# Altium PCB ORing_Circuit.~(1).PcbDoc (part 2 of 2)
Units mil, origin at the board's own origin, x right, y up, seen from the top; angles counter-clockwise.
Board outline 1338.58 x 1378.07 mil, 8 copper layers (Top Layer, Layer 2, Layer 3, Layer 4, Layer 5, Layer 6, Layer 7, Bottom Layer), stack 50.047 mil thick; 34 components, 15 nets, 290 pads, 1023 vias.
Unrouted connection lines stored in the file: 1.
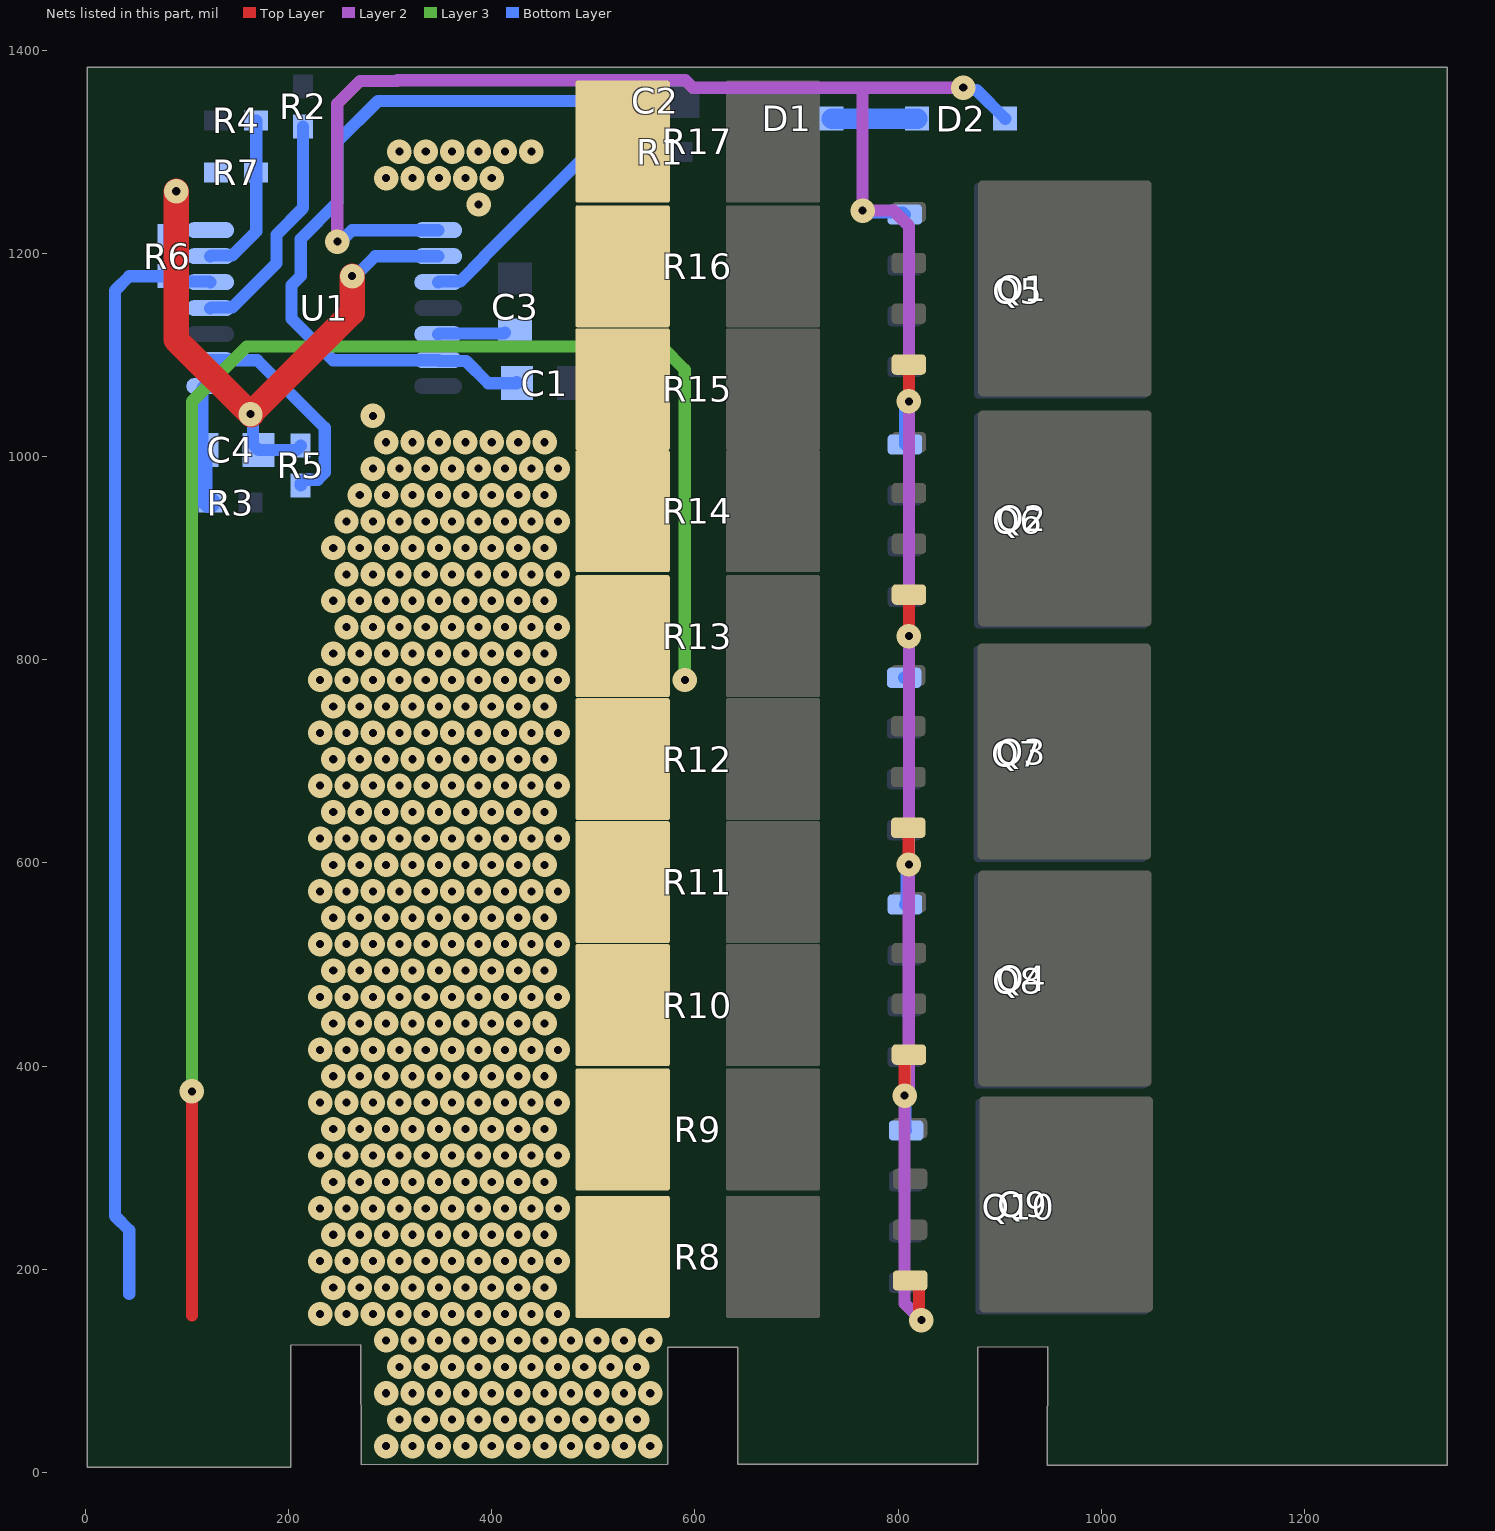
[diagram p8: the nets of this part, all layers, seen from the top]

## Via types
v1: diameter 24, hole 8, Top Layer to Bottom Layer, 1004 vias
v2: diameter 24, hole 8, Top Layer to Bottom Layer, tented both sides, 18 vias
v3: diameter 20, hole 10, Top Layer to Bottom Layer, 1 vias

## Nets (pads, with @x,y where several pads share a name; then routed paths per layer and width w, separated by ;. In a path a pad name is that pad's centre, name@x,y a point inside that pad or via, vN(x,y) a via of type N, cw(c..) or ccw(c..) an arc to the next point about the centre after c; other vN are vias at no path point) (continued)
Iout_SNS: R8.1 R9.1 R10.1 R11.1 R12.1 R13.1 R14.1 R15.1 R16.1 R17.1 | length 1721.9
  Top Layer w12: 104.89,154.61 v2(104.89,375.09)
  Layer 3 w12: v2(104.89,375.09) 104.89,1054.16 158.85,1108.13 567.3,1108.13 590,1085.43 v2(590,780)
  other v1: 296,26 322,26 348,26 374,26 400,26 426,26 452,26 478,26 504,26 530,26 556,26 309,52 335,52 361,52 387,52 413,52 439,52 465,52 491,52 517,52 543,52 296,78 322,78 348,78 374,78 400,78 426,78 452,78 478,78 504,78 530,78 556,78 309,104 335,104 361,104 387,104 413,104 439,104 465,104 491,104 517,104 543,104 296,130 322,130 348,130 374,130 400,130 426,130 452,130 478,130 504,130 530,130 556,130 231,156 257,156 283,156 309,156 335,156 361,156 387,156 413,156 439,156 465,156 244,182 270,182 296,182 322,182 348,182 374,182 400,182 426,182 452,182 231,208 257,208 283,208 309,208 335,208 361,208 387,208 413,208 439,208 465,208 244,234 270,234 296,234 322,234 348,234 374,234 400,234 426,234 452,234 231,260 257,260 283,260 309,260 335,260 361,260 387,260 413,260 439,260 465,260 244,286 270,286 296,286 322,286 348,286 374,286 400,286 426,286 452,286 231,312 257,312 283,312 309,312 335,312 361,312 387,312 413,312 439,312 465,312 244,338 270,338 296,338 322,338 348,338 374,338 400,338 426,338 452,338 231,364 257,364 283,364 309,364 335,364 361,364 387,364 413,364 439,364 465,364 244,390 270,390 296,390 322,390 348,390 374,390 400,390 426,390 452,390 231,416 257,416 283,416 309,416 335,416 361,416 387,416 413,416 439,416 465,416 244,442 270,442 296,442 322,442 348,442 374,442 400,442 426,442 452,442 231,468 257,468 283,468 309,468 335,468 361,468 387,468 413,468 439,468 465,468 244,494 270,494 296,494 322,494 348,494 374,494 400,494 426,494 452,494 231,520 257,520 283,520 309,520 335,520 361,520 387,520 413,520 439,520 465,520 244,546 270,546 296,546 322,546 348,546 374,546 400,546 426,546 452,546 231,572 257,572 283,572 309,572 335,572 361,572 387,572 413,572 439,572 465,572 244,598 270,598 296,598 322,598 348,598 374,598 400,598 426,598 452,598 231,624 257,624 283,624 309,624 335,624 361,624 387,624 413,624 439,624 465,624 244,650 270,650 296,650 322,650 348,650 374,650 400,650 426,650 452,650 231,676 257,676 283,676 309,676 335,676 361,676 387,676 413,676 439,676 465,676 244,702 270,702 296,702 322,702 348,702 374,702 400,702 426,702 452,702 231,728 257,728 283,728 309,728 335,728 361,728 387,728 413,728 439,728 465,728 244,754 270,754 296,754 322,754 348,754 374,754 400,754 426,754 452,754 231,780 257,780 283,780 309,780 335,780 361,780 387,780 413,780 439,780 465,780 244,806 270,806 296,806 322,806 348,806 374,806 400,806 426,806 452,806 257,832 283,832 309,832 335,832 361,832 387,832 413,832 439,832 465,832 244,858 270,858 296,858 322,858 348,858 374,858 400,858 426,858 452,858 257,884 283,884 309,884 335,884 361,884 387,884 413,884 439,884 465,884 244,910 270,910 296,910 322,910 348,910 374,910 400,910 426,910 452,910 257,936 283,936 309,936 335,936 361,936 387,936 413,936 439,936 465,936 270,962 296,962 322,962 348,962 374,962 400,962 426,962 452,962 283,988 309,988 335,988 361,988 387,988 413,988 439,988 465,988 296,1014 322,1014 348,1014 374,1014 400,1014 426,1014 452,1014 283,1040 387,1248 296,1274 322,1274 348,1274 374,1274 400,1274 309,1300 335,1300 361,1300 387,1300 413,1300 439,1300
NetC1_1: C1.1 C2.2 U1.13 | length 743.9
  Bottom Layer w12: C1.1@424.62,1073.08 C1.1@424.62,1072.09 396.58,1072.09 374.59,1094.09 347.97,1094.09 U1.13@347.25,1094.8 243.84,1094.8 203,1135.65 203,1168.55 211.97,1177.52 211.97,1214.19 248,1250.22 248,1310 287.99,1349.99 C2.2@533.44,1349.99
NetC3_2: C3.2 U1.12 | length 66.4
  Bottom Layer w12: U1.12@347.25,1120.4 347.97,1121.11 412.18,1121.11 C3.2@413,1121.93
NetC4_1: C4.1 R3.1 U1.1 | length 125.5
  Bottom Layer w12: C4.1@115.3,1006.49 115.3,1067.48 117.03,1069.21 U1.1@122.85,1069.21
  Bottom Layer w20: C4.1@115.3,1006.49 115.3,960.71 121.52,954.49 R3.1@123.17,954.49
NetD1_1: D1.1 D2.1 | length 84.4
  Bottom Layer w20: D1.1@734.31,1332.49 D2.1@818.69,1332.49
NetR1_1: R1.1 U1.10 | length 252.5
  Bottom Layer w12: U1.10@347.25,1171.58 347.97,1172.29 368.89,1172.29 392.39,1195.8 392.39,1196.54 495.34,1299.49 R1.1@546.32,1299.49
NetR2_1: R2.1 U1.4 | length 228.9
  Bottom Layer w12: U1.4@122.85,1145.99 123.56,1146.7 144.48,1146.7 188,1190.22 188,1218.32 214.28,1244.61 R2.1@214.28,1324.81
NetR4_1: R4.1 R7.2 U1.6 | length 164.4
  Bottom Layer w12: U1.6@122.85,1197.17 123.56,1197.88 144.48,1197.88 168.12,1221.53 R7.2@168.12,1279.33 R4.1@168.12,1330.51
NetR5_2: R5.2 U1.2 | length 214.7
  Bottom Layer w12: U1.2@122.85,1094.8 169.12,1094.8 235.68,1028.25 235.68,984.16 228.65,977.13 215.81,977.13 211.97,973.29 R5.2@211.97,971.32
ORing_CTRL: R6.2 U1.5 | length 1095.5
  Bottom Layer w12: 43.14,175.8 43.14,238.32 29.08,252.38 29.08,1163.42 43.14,1177.48 79.3,1177.48 84.49,1172.29 122.13,1172.29 U1.5@122.85,1171.58
ORing_Gate: D2.2 Q1.4 Q2.4 Q3.4 Q4.4 Q5.4 Q6.4 Q7.4 Q8.4 Q9.4 Q10.4 U1.8 | length 2588.9
  Top Layer w12: v2(806.37,370.88) 806.37,407.29 810.41,411.33 Q4.4@810.59,411.33 ; Q3.4@809.88,634.56 810.18,634.27 810.18,598.64 v2(810.47,598.35) ; Q1.4@810.47,1090.47 810.53,1090.41 810.53,1054.31 v2(810.59,1054.25) ; v2(810.59,823.17) Q2.4@810.59,864.09 ; Q9.4@811.75,188.95 816.49,188.95 820.53,184.91 820.53,152.3 v2(822.82,150)
  Layer 2 w12: v2(248,1211.49) 248,1347.08 270.62,1369.7 306.62,1369.7 307.28,1370.36 590.64,1370.36 598.01,1362.99 765,1362.99 ; v2(822.82,150) 806.37,166.45 v2(806.37,370.88) 806.37,374.12 810.47,378.22 v2(810.47,598.35) 810.53,598.41 810.53,823.11 v2(810.59,823.17) v2(810.59,1054.25) 810.59,1226.83 795.42,1242 v2(765,1242) 765,1362.99 ; v2(864,1362.99) 765,1362.99
  Bottom Layer w12: v2(248,1211.49) 251.25,1211.49 262.51,1222.76 U1.8@347.25,1222.76 ; v2(765,1242) 766.92,1240.08 804.55,1240.08 Q5.4@806.47,1238.15 ; Q7.4@805.88,782.25 806.55,782.25 810.59,786.29 v2(810.59,823.17) ; v2(806.37,370.88) 807.06,370.19 807.06,337.33 Q10.4@807.75,336.64 ; Q8.4@806.59,559.02 808.53,560.96 808.53,596.41 v2(810.47,598.35) ; Q6.4@806.59,1011.77 806.59,1047.01 810.59,1051.01 v2(810.59,1054.25) ; v2(864,1362.99) 866.3,1360.69 877.1,1360.69 D2.2@905.31,1332.49
SGND: C4.2 R5.1 R6.1 R7.1 U1.7 U1.9 | length 606.1
  Top Layer w12: v2@260.22,1179.78 v2(262.51,1177.48)
  Top Layer w25: v2(89.49,1261.06) 89.49,1114.7 v2(162.54,1041.66) ; v2@163.33,1040.86 v2(162.54,1041.66) ; v2(262.51,1177.48) 262.51,1141.63 v2(162.54,1041.66)
  Bottom Layer w12: v2(162.54,1041.66) 164.84,1039.36 164.84,1012.07 C4.2@170.41,1006.49 208.12,1006.49 211.97,1010.33 R5.1@211.97,1010.69 ; v2(262.51,1177.48) 265.57,1177.48 285.26,1197.17 U1.9@347.25,1197.17
pads on no net: Q1.9@888.82,1072.06 Q1.9@888.82,1258.87 Q1.9@900.43,1113.11 Q1.9@900.43,1165.47 Q1.9@900.43,1217.83 Q1.9@945.71,1113.11 Q1.9@945.71,1165.47 Q1.9@945.71,1217.83 Q1.9@951.02,1165.47 Q1.9@990.99,1113.11 Q1.9@990.99,1165.47 Q1.9@990.99,1217.83 Q2.9@888.93,845.68 Q2.9@888.93,1032.49 Q2.9@900.55,886.73 Q2.9@900.55,939.09 Q2.9@900.55,991.45 Q2.9@945.82,886.73 Q2.9@945.82,939.09 Q2.9@945.82,991.45 Q2.9@951.14,939.09 Q2.9@991.1,886.73 Q2.9@991.1,939.09 Q2.9@991.1,991.45 Q3.9@888.23,616.16 Q3.9@888.23,802.97 Q3.9@899.84,657.2 Q3.9@899.84,709.56 Q3.9@899.84,761.92 Q3.9@945.12,657.2 Q3.9@945.12,709.56 Q3.9@945.12,761.92 Q3.9@950.43,709.56 Q3.9@990.39,657.2 Q3.9@990.39,709.56 Q3.9@990.39,761.92 Q4.9@888.93,392.93 Q4.9@888.93,579.74 Q4.9@900.55,433.97 Q4.9@900.55,486.33 Q4.9@900.55,538.7 Q4.9@945.82,433.97 Q4.9@945.82,486.33 Q4.9@945.82,538.7 Q4.9@951.14,486.33 Q4.9@991.1,433.97 Q4.9@991.1,486.33 Q4.9@991.1,538.7 Q5.9@884.82,1069.75 Q5.9@884.82,1256.56 Q5.9@896.43,1110.79 Q5.9@896.43,1163.15 Q5.9@896.43,1215.52 Q5.9@941.71,1110.79 Q5.9@941.71,1163.15 Q5.9@941.71,1215.52 Q5.9@947.02,1163.15 Q5.9@986.99,1110.79 Q5.9@986.99,1163.15 Q5.9@986.99,1215.52 Q6.9@884.93,843.37 Q6.9@884.93,1030.18 Q6.9@896.55,884.41 Q6.9@896.55,936.77 Q6.9@896.55,989.14 Q6.9@941.82,884.41 Q6.9@941.82,936.77 Q6.9@941.82,989.14 Q6.9@947.14,936.77 Q6.9@987.1,884.41 Q6.9@987.1,936.77 Q6.9@987.1,989.14 Q7.9@884.23,613.84 Q7.9@884.23,800.65 Q7.9@895.84,654.89 Q7.9@895.84,707.25 Q7.9@895.84,759.61 Q7.9@941.12,654.89 Q7.9@941.12,707.25 Q7.9@941.12,759.61 Q7.9@946.43,707.25 Q7.9@986.39,654.89 Q7.9@986.39,707.25 Q7.9@986.39,759.61 Q8.9@884.93,390.61 Q8.9@884.93,577.42 Q8.9@896.55,431.66 Q8.9@896.55,484.02 Q8.9@896.55,536.38 Q8.9@941.82,431.66 Q8.9@941.82,484.02 Q8.9@941.82,536.38 Q8.9@947.14,484.02 Q8.9@987.1,431.66 Q8.9@987.1,484.02 Q8.9@987.1,536.38 Q9.9@890.1,170.55 Q9.9@890.1,357.36 Q9.9@901.71,211.59 Q9.9@901.71,263.95 Q9.9@901.71,316.31 Q9.9@946.99,211.59 Q9.9@946.99,263.95 Q9.9@946.99,316.31 Q9.9@952.3,263.95 Q9.9@992.27,211.59 Q9.9@992.27,263.95 Q9.9@992.27,316.31 Q10.9@886.1,168.23 Q10.9@886.1,355.04 Q10.9@897.71,209.28 Q10.9@897.71,261.64 Q10.9@897.71,314 Q10.9@942.99,209.28 Q10.9@942.99,261.64 Q10.9@942.99,314 Q10.9@948.3,261.64 Q10.9@988.27,209.28 Q10.9@988.27,261.64 Q10.9@988.27,314 U1.3 U1.14

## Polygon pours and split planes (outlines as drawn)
SGND on Layer 5 "SGND" (solid, remove dead copper, pour order 85): 50,1280 10,1240 10,516.23 143.65,382.58 143.65,199.68 163.33,180 173.02,180 183.02,190 183.02,1038.88 279.18,1135.04 279.18,1179.78 275.22,1179.78 175,1280
Iout_SNS on Layer 5 "LAYER_5_IOUT_SNS_P055" (solid, remove dead copper, pour order 55): 586.77,810 569.71,792.95 569.71,767.05 586.77,750 586.77,128.23 589.49,125.51 573.26,125.51 573.26,5.91 271.31,7.89 271.31,125.49 202,125.49 202,1367.64 217.43,1383.07 586.77,1383.07
12VB on Layer 5 "LAYER_5_12VB_P069" (solid, remove dead copper, pour order 69): 864,1383.07 864,172.44 912.83,123.61 946.83,123.74 946.83,7.3 1340.53,7.3 1340.53,1302.71 1261.79,1381.45
12VA on Layer 5 "LAYER_5_12VA_P074" (solid, remove dead copper, pour order 74): 613,780 635.96,757.04 635.96,732.96 613,710 613,128.87 608.22,124.09 642.28,124.09 642.28,7.02 878.86,6.85 878.86,123.48 879,145 837,145 835,147 838,150 838,1382.93 613,1385
no net on Top Solder "NONET_L-01_P-001" (solid): 271.31,126.41 271.31,7.89 573.26,5.91 573.26,125.51
no net on Top Solder "NONET_L-01_P-001" (solid): 642.11,129.15 642.11,6.85 878.86,6.85 877.42,129.15
no net on Top Solder "NONET_L-01_P-001" (solid): 946.83,130.88 946.83,7.3 1262.4,7.3 1261.17,130.88
no net on Top Solder "NONET_L-01_P-001" (solid): 1.94,125.49 201,125.49 201,7.74 202,6.74 1.94,6.74
no net on Top Solder "NONET_L-01_P-001" (solid): 4,222 189,222 189,105.07 190.07,104 174.73,88.66 1.94,88.66
no net on Top Solder "NONET_L-01_P-001" (solid): 296,1383.07 296,970.29 202,876.29 202,159.86 238.99,122.87 271.31,122.87 271.31,7.74 273.28,5.77 573.26,5.77 573.26,146 479,146 478,145 477,146 477,1385
no net on Top Solder "NONET_L-01_P-001" (solid): 907,1282 915,1274 1063,1274 1063,130.88 1055.56,123.44 945.6,123.44 945.6,7 1340.53,7.37 1340.53,1302.71 1260.16,1383.07 907,1383.07
SGND on Bottom Layer "BOTTOM_LAYER_SGND_P041" (solid, remove dead copper, pour order 41): 54.78,1202.33 55.13,1201.98 148.57,1201.98 148.57,1301.31 147.65,1302.23 75.01,1302.23 54.78,1282
Iout_SNS on Bottom Layer "BOTTOM_LAYER_IOUT_SNS_P058" (solid, remove dead copper, pour order 58): 586.77,810 563.3,786.53 563.3,752.82 586.77,729.35 586.77,128.09 589.49,125.36 573.26,125.36 573.26,5.77 271.31,7.74 271.31,125.34 202,125.34 202,1027.23 586.77,1027.23
12VA on Bottom Layer "BOTTOM_LAYER_12VA_P077" (solid, remove dead copper, pour order 77): 613,780 634.73,758.27 634.73,740.09 613,718.35 613,128.87 608.22,124.09 642.28,124.09 642.28,7.02 642.11,6.85 878.86,6.85 878.86,123.48 879,123.62 879,145 837,145 835,147 838,150 838,1382.93 613,1385
12VB on Bottom Layer "BOTTOM_LAYER_12VB_P072" (solid, remove dead copper, pour order 72): 864,1383.07 864,172.44 912.83,123.61 946.83,123.74 946.83,7.3 1340.53,7.3 1340.53,1302.71 1261.79,1381.45
SGND on Layer 6 "SGND" (solid, remove dead copper, pour order 83): 50,1280 10,1240 10,516.23 143.65,382.58 143.65,199.68 163.33,180 173.02,180 183.02,190 183.02,1038.88 279.18,1135.04 279.18,1179.78 275.22,1179.78 175,1280
Iout_SNS on Layer 6 "LAYER_6_IOUT_SNS_P056" (solid, remove dead copper, pour order 56): 586.77,810 571.68,794.91 571.68,765.09 586.77,750 586.77,128.23 589.49,125.51 573.26,125.51 573.26,5.91 271.31,7.89 271.31,125.49 202,125.49 202,1367.64 217.43,1383.07 586.77,1383.07
12VB on Layer 6 "LAYER_6_12VB_P070" (solid, remove dead copper, pour order 70): 864,1383.07 864,172.44 912.83,123.61 946.83,123.74 946.83,7.3 1340.53,7.3 1340.53,1302.71 1261.79,1381.45
12VA on Layer 6 "LAYER_6_12VA_P075" (solid, remove dead copper, pour order 75): 613,784.04 640,757.04 640,737 613,710 613,128.87 608.22,124.09 642.28,124.09 642.28,7.02 642.11,6.85 878.86,6.85 878.86,123.48 879,123.62 879,145 837,145 835,147 838,150 838,1382.93 613,1385
no net on Bottom Solder "NONET_L-01_P-001" (solid): 1.94,125.49 202,125.49 202,6.74 1.94,6.74
no net on Bottom Solder "NONET_L-01_P-001" (solid): 4,222 189,222 189,105.07 190.07,104 174.73,88.66 1.94,88.66
no net on Bottom Solder "NONET_L-01_P-001" (solid): 271.31,126.41 271.31,7.89 573.26,5.91 573.26,125.51
no net on Bottom Solder "NONET_L-01_P-001" (solid): 642.11,129.15 642.11,6.85 878.86,6.85 877.42,129.15
no net on Bottom Solder "NONET_L-01_P-001" (solid): 946.83,130.88 946.83,7.3 1262.4,7.3 1261.17,130.88
no net on Bottom Solder "NONET_L-01_P-001" (solid): 296,1029.49 296,973.98 202,879.98 202,163.55 238.99,126.56 271.31,126.56 271.31,11.43 273.28,9.46 573.26,9.46 573.26,149.69 573.26,1032.44
no net on Bottom Solder "NONET_L-01_P-001" (solid): 946.79,1277.85 1064.19,1277.85 1064.19,134.73 1056.75,127.29 946.79,127.29 946.79,10.85 1340.53,11.21 1340.53,1307.75 1261.35,1386.92 946.79,1386.92
no net on Bottom Solder "NONET_L-01_P-001" (solid): 613,1211.49 613,123.48 613.61,122.87 777,122.87 777,1211.49
SGND on Top Layer "SGND" (solid, remove dead copper, pour order 79): 50,1280 10,1240 10,516.23 143.65,382.58 143.65,90 183.02,90 183.02,1038.88 279.18,1135.04 279.18,1179.78 275.22,1179.78 175,1280
Iout_SNS on Top Layer "TOP_LAYER_IOUT_SNS_P051" (solid, remove dead copper, pour order 51): 573.26,5.91 573.26,125.51 589.49,125.51 586.77,128.23 586.77,1383.07 217.43,1383.07 202,1367.64 202,125.49 271.31,125.49 271.31,7.89
12VA on Top Layer "TOP_LAYER_12VA_P059" (solid, remove dead copper, pour order 59): 613,1385 613,128.87 608.22,124.09 642.28,124.09 642.28,7.02 642.11,6.85 878.86,6.85 878.86,123.48 879,123.62 879,145 837,145 835,147 838,150 838,1382.93
12VB on Top Layer "TOP_LAYER_12VB_P063" (solid, remove dead copper, pour order 63): 864,1383.07 864,172.44 912.83,123.61 946.83,123.74 946.83,7.3 1340.53,7.3 1340.53,1302.71 1261.79,1381.45
Iout_SNS on Layer 2 "LAYER_2_IOUT_SNS_P052" (solid, remove dead copper, pour order 52): 586.77,810 569.71,792.95 569.71,765.95 586.77,748.9 586.77,741.65 586.77,128.23 589.49,125.51 573.26,125.51 573.26,5.91 271.31,7.89 271.31,125.49 202,125.49 177.51,150 20,150 10,160 10,1110.92 39.09,1140.01 202,1139.91 202,1367.64 217.43,1383.07 586.77,1383.07
12VA on Layer 2 "LAYER_2_12VA_P062" (solid, remove dead copper, pour order 62): 613,780 640,753 640,740 613.47,713.47 613,710 613,128.87 608.22,124.09 642.28,124.09 642.28,7.02 642.11,6.85 878.86,6.85 878.86,123.48 879,123.62 879,145 837,145 835,147 838,150 838,1382.93 613,1385
12VB on Layer 2 "LAYER_2_12VB_P066" (solid, remove dead copper, pour order 66): 864,1383.07 864,172.44 912.83,123.61 946.83,123.74 946.83,7.3 1340.53,7.3 1340.53,1302.71 1261.79,1381.45
Iout_SNS on Layer 3 "LAYER_3_IOUT_SNS_P053" (solid, remove dead copper, pour order 53): 573.26,5.91 573.26,125.51 573.26,1087 202,1087 202,125.49 271.31,125.49 271.31,7.89
12VA on Layer 3 "LAYER_3_12VA_P064" (solid, remove dead copper, pour order 64): 640,757.04 640,728.65 613,701.65 613,128.87 608.22,124.09 642.28,124.09 642.28,7.02 878.86,6.85 878.86,123.48 879,145 837,145 835,147 838,150 838,1382.93 640,1384.75
12VB on Layer 3 "LAYER_3_12VB_P067" (solid, remove dead copper, pour order 67): 864,1383.07 864,172.44 912.83,123.61 946.83,123.74 946.83,7.3 1340.53,7.3 1340.53,1302.71 1261.79,1381.45
Iout_SNS on Layer 4 "LAYER_4_IOUT_SNS_P054" (solid, remove dead copper, pour order 54): 586.77,807.05 569.71,790 570,789.71 570,758.41 586.77,741.65 586.77,128.23 589.49,125.51 573.26,125.51 573.26,5.91 271.31,7.89 271.31,125.49 202,125.49 202,128 180,150 20,150 10,160 10,1110 40,1140 202,1140 202,1367.64 217.43,1383.07 586.77,1383.07
12VB on Layer 4 "LAYER_4_12VB_P068" (solid, remove dead copper, pour order 68): 864,1383.07 864,172.44 912.83,123.61 946.83,123.74 946.83,7.3 1340.53,7.3 1340.53,1302.71 1261.79,1381.45
12VA on Layer 4 "LAYER_4_12VA_P073" (solid, remove dead copper, pour order 73): 613,780 640,753 640,737 613,710 613,128.87 608.22,124.09 642.28,124.09 642.28,7.02 642.11,6.85 878.86,6.85 878.86,123.48 879,123.62 879,145 837,145 835,147 838,150 838,1382.93 613,1385
SGND on Layer 7 "SGND" (solid, remove dead copper, pour order 81): 50,1280 10,1240 10,516.23 143.65,382.58 143.65,199.68 163.33,180 173.02,180 183.02,190 183.02,1038.88 279.18,1135.04 279.18,1179.78 275.22,1179.78 175,1280
Iout_SNS on Layer 7 "LAYER_7_IOUT_SNS_P057" (solid, remove dead copper, pour order 57): 586.77,810 569.71,792.95 569.71,765.92 586.77,750 586.77,128.23 589.49,125.51 573.26,125.51 573.26,5.91 271.31,7.89 271.31,125.49 202,125.49 202,1367.64 217.43,1383.07 586.77,1383.07
12VB on Layer 7 "LAYER_7_12VB_P071" (solid, remove dead copper, pour order 71): 862.77,1382.78 862.77,172.14 911.6,123.31 945.6,123.44 945.6,7 1340.53,7 1340.53,1301.19 1260.56,1381.15
12VA on Layer 7 "LAYER_7_12VA_P076" (solid, remove dead copper, pour order 76): 613,780 635.96,757.04 635.96,732.96 613,710 613,128.87 608.22,124.09 642.28,124.09 642.28,7.02 878.86,6.85 878.86,123.48 879,145 837,145 835,147 838,150 838,1382.93 613,1385

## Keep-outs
Keep-Out Layer:
  text ".Layer_Name" at 577,-858.49 h60

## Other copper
Top Layer:
  region net Iout_SNS: 121.02,202.68 109.21,214.49 93.46,214.49 81.65,202.68 81.65,5.83 121.02,5.83
  region net SGND: 183.02,201.68 171.21,213.49 155.46,213.49 143.65,201.68 143.65,4.83 183.02,4.83
  region net 12VA: 60.68,202.19 48.87,214 33.13,214 21.32,202.19 21.32,5.34 60.68,5.34
  text ".Layer_Name" at 577,-858.49 h60
Bottom Layer:
  region net 12VS: 81.06,202.67 92.87,214.48 108.62,214.48 120.43,202.67 120.43,5.82 81.06,5.82
  region net SGND: 143.23,202.61 155.04,214.42 170.79,214.42 182.6,202.61 182.6,5.76 143.23,5.76
  region net ORing_CTRL: 21.32,202.67 33.13,214.48 48.87,214.48 60.68,202.67 60.68,5.82 21.32,5.82
  text ".Layer_Name" at 577,-858.49 h60

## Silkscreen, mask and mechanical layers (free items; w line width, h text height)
Top Overlay:
  text ".Layer_Name" at 577,-858.49 h60
Bottom Overlay:
  text "ORING DC" at 23.46,248 h80 r270
  text "PMP23126 RevA" at 93.46,248 h80 r270
  text ".Layer_Name" at 577,-858.49 h60
Top Paste:
  text ".Layer_Name" at 577,-858.49 h60
Bottom Paste:
  text ".Layer_Name" at 577,-858.49 h60
Top Solder:
  text ".Layer_Name" at 577,-858.49 h60
  text ".Layer_Name" at 577,-858.49 h60
Bottom Solder:
  text ".Layer_Name" at 577,-858.49 h60
Drill Guide:
  text ".Layer_Name" at 577,-858.49 h60
M1 Board Outline:
  lines w10: 202,5 1.94,5 1.94,1383.07 1340.53,1383.07 1340.53,7 946.83,7.25 947.33,123.74 878.33,123.48 878.33,7.94 642.11,7.94 642.11,123.48 573.11,123.48 573.42,7.94 271.31,7.69 271.31,125.8 ; 202,7 202,125.11 ; 202,125.23 271,125.49
  text ".Layer_Name" at 577,-858.49 h60
M2 Board Dimensions:
  rectangle: 125,-400 500,-275
  rectangle: 0,-275 125,-150
  lines w7: 0,-275 1000,-275 ; 125,-400 125,-150 ; 250,-400 250,-150 ; 500,-400 500,-150 ; 750,-400 750,-150 ; 0,-400 0,-150 1000,-150 1000,-400 0,-400
  text ".Layer_Name" at 577,-858.49 h60
M3 3D STEP Top:
  text ".Layer_Name" at 577,-858.49 h60
M4 3D STEP Bottom:
  text ".Layer_Name" at 577,-858.49 h60
M5 Assembly Top:
  lines w10: -292,-930.17 6308,-930.17 ; -292,-726.83 6310,-726.83 ; -292,-523.5 -292,-1133.5 3713,-1133.5 6310,-1133.5 6310,-523.5 -291.5,-523.5 -291.5,-1133.5 1284,-1133.5 ; 2173,-1133.5 2173,-523.5 ; 3440,-726.83 3440,-523.5 ; 4280,-726.83 4280,-523.5 ; 4902,-1140 4902,-937.17
  text "COMPONENTS MARKED 'DNP' SHOULD NOT BE POPULATED." at 1153.5,-318.5 h60
  text "ASSEMBLY VARIANT:" at 1153,-434 h60
  text ".VariantName" at 2189,-434 h60
  text "PCB VIEWED FROM TOP SIDE" at -228.5,-655.67 h60
  text "BOARD #:" at 2248,-655.67 h60
  text ".PRJ_Number" at 2793.5,-655.67 h60
  text "REV:" at 3638,-655.67 h60
  text ".PCB_Rev" at 3929.5,-655.67 h60
  text "SVN REV:" at 4476,-655.67 h60
  text ".VersionControl_RevNumber" at 4982,-655.67 h60
  text "TID #:" at 2248,-859 h60
  text ".TID" at 2793.5,-859 h60
  text "PLOT NAME =" at -228.5,-1064.34 h60
  text ".plot_File_Name" at 577,-1064.34 h60
  text "GENERATED    :" at 2250,-1064.34 h60
  text ".Print_Date" at 3119.5,-1064.34 h60
  text ".Print_Time" at 3848.5,-1064.34 h60
  text "TEXAS INSTRUMENTS" at 5113,-1064.34 h60
M6 Assembly Bottom:
  lines w10: -292.5,-727.33 6309.5,-727.33 ; -290.5,-930.67 6309.5,-930.67 ; 1115.5,-1140.5 1115.5,-937.67 ; 1737.5,-727.33 1737.5,-524 ; 2577.5,-727.33 2577.5,-524 ; 3844.5,-1134 3844.5,-524 ; 4733.5,-1134 6309,-1134 6309,-524 -292.5,-524 -292.5,-1134 2304.5,-1134 6309.5,-1134 6309.5,-524
  text "COMPONENTS MARKED 'DNP' SHOULD NOT BE POPULATED." at 6102,-318 h60
  text ".VariantName" at 5058,-434 h60
  text "ASSEMBLY VARIANT:" at 6097,-434 h60
  text ".VersionControl_RevNumber" at 1035.5,-656.17 h60
  text "SVN REV:" at 1541.5,-656.17 h60
  text ".PCB_Rev" at 2088,-656.17 h60
  text "REV:" at 2379.5,-656.17 h60
  text ".PRJ_Number" at 3224,-656.17 h60
  text "BOARD #:" at 3769.5,-656.17 h60
  text "PCB VIEWED FROM BOTTOM SIDE" at 6246,-656.17 h60
  text ".TID" at 3224,-859.5 h60
  text "TID #:" at 3769.5,-859.5 h60
  text "TEXAS INSTRUMENTS" at 904.5,-1064.84 h60
  text ".Print_Time" at 2169,-1064.84 h60
  text ".Print_Date" at 2898,-1064.84 h60
  text "GENERATED    :" at 3767.5,-1064.84 h60
  text ".plot_File_Name" at 5440.5,-1064.84 h60
  text "PLOT NAME =" at 6246,-1064.84 h60
M9 Title Sheet:
  drawing of 57 lines, arcs and shapes, not listed
  text "1" at 739.84,8036.5 h70
  text "2" at 3235.5,8036.5 h70
  text "3" at 5724.84,8036.5 h70
  text "4" at 8231.51,8036.5 h70
  text "5" at 10730.5,8036.5 h70
  text "6" at 13235.5,8036.5 h70
  text "A" at -416.5,6893.5 h70
  text "A" at 14383.5,6893.5 h70
  text "B" at -416.5,4513.5 h70
  text "B" at 14383.5,4513.5 h70
  text "C" at -416.5,2138.5 h70
  text "C" at 14383.5,2138.5 h70
  text "PROJECT TITLE:" at 11343.5,277.5 h45
  text ".PRJ_Title" at 11393.5,144.17 h70
  text "DESIGNED FOR:" at 11343.5,-23.5 h45
  text ".PRJ_Customer" at 11393.5,-163.5 h70
  text "D" at -416.5,-231.5 h70
  text "D" at 14383.5,-231.5 h70
  text "FILE NAME:" at 11343.5,-323.5 h45
  text ".PCB_File_Name_No_Path" at 11393.5,-443.5 h70
  text "Texas Instruments (TI) and/or its licensors do not warrant the accuracy or completeness of this specification" at 6374,-605.34 h45
  text "ENGINEER:" at 11343.5,-613.5 h45
  text "LAYOUT BY:" at 12848.5,-613.5 h45
  text "or any information contained therein. TI and/or its licensors do not warrant that this design will meet" at 6329.01,-718 h45
  text ".PRJ_Engineer" at 11393.5,-768.49 h70
  text ".PCB_Layout" at 12899,-768.49 h70
  text "the specifications, will be suitable for your application or fit for any particular purpose, or will operate in" at 6329.01,-830.67 h45
  text ".Layer_Name" at 577,-858.49 h60
  text "ALTIUM DESIGNER VERSION:" at 12848.5,-923.5 h45
  text "an implementation. TI and/or its licensors do not warrant that the design is production worthy. You should" at 6329.01,-943.33 h45
  text "completely validate and test your design implementation to confirm the system functionality for your application." at 6374,-1056 h45
  text ".print_Scale" at 11393.5,-1056.83 h70
  text ".Application_BuildNumber" at 12899,-1056.83 h70
  text "1" at 739.84,-1263.5 h70
  text "2" at 3235.5,-1263.5 h70
  text "3" at 5724.84,-1263.5 h70
  text "4" at 8231.51,-1263.5 h70
  text "5" at 10730.5,-1263.5 h70
  text "6" at 13235.5,-1263.5 h70
M10 Fab Notes:
  drawing of 189 lines, arcs and shapes, not listed
  text "DESIGN INFORMATION" at 12382.02,6356.17 h60
  text "MIN. TRACK WIDTH:" at 11737.46,6224.05 h60
  text "8" at 12833.7,6224.05 h60
  text "MIL" at 12988.46,6224.05 h60
  text "7.874" at 12667.32,6102.36 h60
  text "MIN. CLEARANCE:" at 11737.46,6099.92 h60
  text "MIL" at 12988.46,6099.92 h60
  text "MIN. VIA PAD SIZE:" at 11737.46,5975.8 h60
  text "24" at 12803.71,5975.8 h60
  text "MIL" at 12988.46,5975.8 h60
  text "0.05mm (2MIL)" at 12432.46,5845.9 h60
  text "MINIMUM ANNULAR RING" at 11408.23,5837.67 h60
  text "EXTERNAL" at 13140.46,5837.67 h60
  text "PER" at 11608.23,5727.55 h60
  text "IPC-D-275 CLASS 2 LEVEL C" at 11828.23,5727.54 h60
  text "MIL, HOLES" at 13316.46,5627.07 h60
  text "+/-" at 12924,5618.48 h60
  text "+/-" at 13778,5618.48 h60
  text "REGISTRATION TOLERANCES:" at 11408.23,5617.42 h60
  text "METAL" at 12608,5617.42 h60
  text "5" at 13184.2,5617.42 h60
  text "3" at 14017.2,5617.42 h60
  text "MIL" at 14133.46,5617.42 h60
  text "HOLE SIZE TOLERANCE (UNLESS OTHERWISE SPECIFIED):" at 11408.23,5519.1 h60
  text "+/-" at 13778,5516.23 h60
  text "3" at 14017.2,5515.17 h60
  text "MIL" at 14133.46,5515.17 h60
  text "MATERIAL:" at 11333.46,5377.52 h60
  text "FR-4 High Tg" at 12319.9,5249 h60
  text "X" at 12175.46,5241.01 h60
  text "FR-408" at 11754.46,5236.49 h60
  text "OTHER" at 13242.46,5236.49 h60
  text "62 MIL (1.6mm) +/-10%" at 12074.56,5093.46 h60
  text "X" at 11954.46,5091.01 h60
  text "THICKNESS:" at 11408.23,5085.24 h60
  text "OTHER" at 13359.46,5085.24 h60
  text "TOLERANCE:" at 11408.23,4946.92 h60
  text "X" at 12256.46,4946.92 h60
  text "ANSI IPC-6012 TYPE 3 CLASS 2" at 12434.48,4946.92 h60
  text "OTHER +/-" at 12434.46,4802.73 h60
  text "BOW & TWIST:" at 11408.23,4657.54 h60
  text "X" at 12256.46,4657.54 h60
  text "ANSI IPC-6012 TYPE 3 CLASS 2" at 12434.48,4657.54 h60
  text "OTHER +/-" at 12434.46,4510.85 h60
  text "DRILLING:" at 11333.46,4380.23 h60
  text "NC_DRILL FILES" at 13094.46,4275.04 h60
  text "REFERENCE:" at 11408.23,4271.1 h60
  text "X" at 12065.46,4271.01 h60
  text "AS SHOWN" at 12243.46,4271.1 h60
  text "X" at 12966.46,4271.1 h60
  text "OTHER" at 13392.46,4128.85 h60
  text "PTH COPPER THICKNESS:" at 11407.91,4125.32 h60
  text "X" at 12547.14,4125.32 h60
  text "20-30 um" at 12675.14,4125.32 h60
  text "BOARD FINISH:" at 11333.46,3977.73 h60
  text "SILKSCREEN:" at 11488.68,3867.6 h60
  text "X" at 12446.46,3867.6 h60
  text "TOP" at 12563.46,3867.6 h60
  text "X" at 12956.46,3867.6 h60
  text "BOTTOM" at 13074.46,3867.6 h60
  text "SILKSCREEN COLOR:" at 11488.68,3712.41 h60
  text "X" at 12445.46,3712.41 h60
  text "WHITE" at 12563.46,3712.41 h60
  text "OTHER" at 13074.46,3712.41 h60
  text "X" at 12576.46,3568.96 h60
  text "GREEN" at 12694.46,3568.96 h60
  text "OTHER" at 13312.46,3568.96 h60
  text "SOLDER RESIST COLOR:" at 11488.68,3562.1 h60
  text "X" at 12576.46,3414.71 h60
  text "MATTE" at 12694.46,3414.71 h60
  text "SEMI-GLOSS" at 13312,3414.07 h60
  text "IMMERSION GOLD (ENIG)" at 12394.46,3241.94 h60
  text "ENEPIG" at 13732,3234.72 h60
  text "SURFACE FINISH:" at 11333.46,3233.72 h60
  text "X" at 12216.46,3233.72 h60
  text "IMM. TIN/SILVER OR EQUIV" at 11663,3096.4 h60
  text "OTHER" at 13094.46,3092.47 h60
  text "ARRAY/PANEL:" at 11333.46,2937.09 h60
  text "CUT AND TRIM PER M1 BOARD OUTLINE" at 12394.46,2928.87 h60
  text "N.C. ROUTE" at 12394.46,2792.9 h60
  text "X" at 13082.46,2792.9 h60
  text "V. SCORE" at 13260.46,2792.9 h60
  text "CERTIFICATION:" at 11333.46,2663.77 h60
  text "MATERIALS AND WORKMANSHIP FOR ALL PCBS" at 12058.46,2663.77 h60
  text "TO MEET OR EXCEED THE REQUIREMENTS OF:" at 12058.46,2569.71 h60
  text "X" at 11695.97,2441.08 h60
  text "ANSI IPC-A-600F CLASS ->" at 11823.96,2441.08 h60
  text "X" at 13471.97,2441.08 h60
  text "2" at 13581.96,2441.08 h60
  text "1" at 13266.96,2439.58 h60
  text "3" at 13935.96,2439.58 h60
  text "X" at 12507.97,2293.39 h60
  text "RoHS" at 12635.96,2293.39 h60
  text "OTHER" at 13280.36,2293.39 h60
  text "PER ORDER" at 13677.42,2293.39 h60
  text "ALL BOARDS MUST MEET OR EXCEED UL94-V0 REQUIREMENTS." at 11361,2139.57 h60
  text "PCB MUST BEAR THE UL94V-0 UL REGISTERED MATERIAL ID NUMBER" at 11361,2023.5 h60
  text "ADDITIONAL REQUIREMENTS:" at 11333.46,1854.08 h60
  text "MICROSECTION:" at 11408.23,1746.95 h60
  text "YES" at 12313.96,1746.95 h60
  text "REQUIRED" at 13175.46,1602.62 h60
  text "BARE BOARD ELEC. TEST:" at 11408.23,1599.76 h60
  text "NONE" at 12713.96,1599.76 h60
  text "X" at 13057.46,1599.76 h60
  text "PER ORDER" at 13767.46,1599.76 h60
  text "XX MIL VIAS REQUIRE NON-CONDUCTIVE FILL AND PLANARIZE" at 11576.38,1394.82 h59
  text "XX MIL VIAS REQUIRE CONDUCTIVE FILL AND PLANARIZE" at 11584.38,1290.84 h60
  text "OUTER XX MIL TRACES REQUIRE 50 OHM SINGLE-ENDED IMPEDANCE" at 11583.39,1127.46 h58
  text "LAYER 2 & 3 (INNER LAYERS) XX MIL WIDE, XX MIL SPACE / TRACES REQUIRE 100 OHM DIFFERENTIAL IMPEDANCE" at 11575.39,891.74 h60
  text ".Layer_Name" at 577,-858.49 h60
M11 Gerber Information:
  lines w10: -292,-930.17 6308,-930.17 ; -292,-726.83 6310,-726.83 ; -292,-523.5 -292,-1133.5 3713,-1133.5 6310,-1133.5 6310,-523.5 -291.5,-523.5 -291.5,-1133.5 1284,-1133.5 ; 2173,-1133.5 2173,-523.5 ; 3440,-726.83 3440,-523.5 ; 4280,-726.83 4280,-523.5 ; 4902,-1140 4902,-937.17
  text "ALL ARTWORK VIEWED FROM TOP SIDE" at -228.5,-655.67 h60
  text "BOARD #:" at 2248,-655.67 h60
  text ".PRJ_Number" at 2793.5,-655.67 h60
  text "REV:" at 3638,-655.67 h60
  text ".PCB_Rev" at 3929.5,-655.67 h60
  text "SVN REV:" at 4476,-655.67 h60
  text ".VersionControl_RevNumber" at 4982,-655.67 h60
  text "LAYER NAME =" at -228.5,-858.49 h60
  text "TID #:" at 2248,-859 h60
  text ".TID" at 2793.5,-859 h60
  text "PLOT NAME =" at -228.5,-1064.34 h60
  text ".plot_File_Name" at 577,-1064.34 h60
  text "GENERATED    :" at 2250,-1064.34 h60
  text ".Print_Date" at 3119.5,-1064.34 h60
  text ".Print_Time" at 3848.5,-1064.34 h60
  text "TEXAS INSTRUMENTS" at 5113,-1064.34 h60
M12 Stackup:
  drawing of 503 lines, arcs and shapes, not listed
  text "Layer" at 5070.19,6530.01 h60
  text "Name" at 5480.11,6530.01 h60
  text "Material" at 6409.85,6530.01 h60
  text "Thickness" at 7269.62,6530.01 h60
  text "Constant" at 7919.45,6530.01 h60
  text "Board Layer Stack" at 8489.31,6530.01 h60
  text "Top Overlay" at 5480.11,6410.01 h60
  text "Top Solder" at 5480.11,6290.01 h60
  text "Solder Resist" at 6409.85,6290.01 h60
  text "0.40mil" at 7269.62,6290.01 h60
  text "3.5" at 7919.45,6290.01 h60
  text "1" at 5070.19,6170.01 h60
  text "Top Layer" at 5480.11,6170.01 h60
  text "2.76mil" at 7269.62,6170.01 h60
  text "Dielectric 1" at 5480.11,6050.01 h60
  text "Core-009" at 6409.85,6050.01 h60
  text "4.00mil" at 7269.62,6050.01 h60
  text "4.5" at 7919.45,6050.01 h60
  text "2" at 5070.19,5930.01 h60
  text "Layer 2" at 5480.11,5930.01 h60
  text "2.76mil" at 7269.62,5930.01 h60
  text "Dielectric 3" at 5480.11,5810.01 h60
  text "Core-009" at 6409.85,5810.01 h60
  text "4.00mil" at 7269.62,5810.01 h60
  text "4.5" at 7919.45,5810.01 h60
  text "3" at 5070.19,5690.01 h60
  text "Layer 3" at 5480.11,5690.01 h60
  text "2.76mil" at 7269.62,5690.01 h60
  text "Dielectric 5" at 5480.11,5570.01 h60
  text "Core-009" at 6409.85,5570.01 h60
  text "4.00mil" at 7269.62,5570.01 h60
  text "4.5" at 7919.45,5570.01 h60
  text "4" at 5070.19,5450.01 h60
  text "Layer 4" at 5480.11,5450.01 h60
  text "2.76mil" at 7269.62,5450.01 h60
  text "Dielectric1" at 5480.11,5330.01 h60
  text "Core-009" at 6409.85,5330.01 h60
  text "4.00mil" at 7269.62,5330.01 h60
  text "4.5" at 7919.45,5330.01 h60
  text "5" at 5070.19,5210.01 h60
  text "Layer 5" at 5480.11,5210.01 h60
  text "2.76mil" at 7269.62,5210.01 h60
  text "Dielectric 6" at 5480.11,5090.01 h60
  text "Core-009" at 6409.85,5090.01 h60
  text "4.00mil" at 7269.62,5090.01 h60
  text "4.5" at 7919.45,5090.01 h60
  text "6" at 5070.19,4970.01 h60
  text "Layer 6" at 5480.11,4970.01 h60
  text "2.76mil" at 7269.62,4970.01 h60
  text "Dielectric 4" at 5480.11,4850.01 h60
  text "Core-009" at 6409.85,4850.01 h60
  text "4.00mil" at 7269.62,4850.01 h60
  text "4.5" at 7919.45,4850.01 h60
  text "7" at 5070.19,4730.01 h60
  text "Layer 7" at 5480.11,4730.01 h60
  text "2.76mil" at 7269.62,4730.01 h60
  text "Dielectric 2" at 5480.11,4610.01 h60
  text "Core-009" at 6409.85,4610.01 h60
  text "4.00mil" at 7269.62,4610.01 h60
  text "4.5" at 7919.45,4610.01 h60
  text "8" at 5070.19,4490.01 h60
  text "Bottom Layer" at 5480.11,4490.01 h60
  text "2.76mil" at 7269.62,4490.01 h60
  text "Bottom Solder" at 5480.11,4370.01 h60
  text "Solder Resist" at 6409.85,4370.01 h60
  text "0.40mil" at 7269.62,4370.01 h60
  text "3.5" at 7919.45,4370.01 h60
  text "Bottom Overlay" at 5480.11,4250.01 h60
  text ".Layer_Name" at 577,-858.49 h60
M13 Component Bodies Top:
  text ".Layer_Name" at 577,-858.49 h60
M14 Component Bodies Bottom:
  text ".Layer_Name" at 577,-858.49 h60
M15 Courtyards Top:
  text ".Layer_Name" at 577,-858.49 h60
M16 Courtyards Bottom:
  text ".Layer_Name" at 577,-858.49 h60
Drill Drawing:
  circle w10: c5363.72,3165.96 r27.63
  lines w10: 5336.09,3262.66 5391.34,3262.66 5391.34,3317.91 5336.09,3317.91 5336.09,3262.66
  lines w12: 5286,3101.04 8517.49,3101.04 ; 5286,3349.68 8517.49,3349.68 ; 5623.86,2976.72 5623.86,3474 ; 5955.86,2976.72 5955.86,3474 ; 6592.43,2976.72 6592.43,3474 ; 6851.57,2976.72 6851.57,3474 ; 7226.72,2976.72 7226.72,3474 ; 7951.05,2976.72 7951.05,3474 ; 5286,2976.72 8517.49,2976.72 8517.49,3474 5286,3474 5286,2976.72
  text "Symbol" at 5360.59,3386.98 h72
  text "Quantity" at 5661.16,3386.98 h72
  text "Finished Hole Size" at 5993.16,3386.98 h72
  text "Plated" at 6629.72,3386.98 h72
  text "Hole Type" at 6888.86,3386.98 h72
  text "Drill Layer Pair" at 7264.02,3386.98 h72
  text "Hole Tolerance" at 7988.35,3386.98 h72
  text "1022" at 5661.16,3262.66 h60
  text "8.00mil (0.203mm)" at 5993.16,3262.66 h60
  text "PTH" at 6629.72,3262.66 h60
  text "Round" at 6888.86,3262.66 h60
  text "Top Layer - Bottom Layer" at 7264.02,3262.66 h60
  text "1" at 5661.16,3138.34 h60
  text "10.00mil (0.254mm)" at 5993.16,3138.34 h60
  text "PTH" at 6629.72,3138.34 h60
  text "Round" at 6888.86,3138.34 h60
  text "Top Layer - Bottom Layer" at 7264.02,3138.34 h60
  text "1023 Total" at 5661.16,3014.02 h60
  text ".Layer_Name" at 577,-858.49 h60
M17 Embedded Cavity:
  text ".Layer_Name" at 577,-858.49 h60
M18 Embedded Assembly:
  text ".Layer_Name" at 577,-858.49 h60
M19 Embedded Keepout:
  text ".Layer_Name" at 577,-858.49 h60

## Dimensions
0,0 to 202,5 on M2 Board Dimensions
0,0 to 271,125.49 on M2 Board Dimensions
0,-400 to 1000,-400 on M2 Board Dimensions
